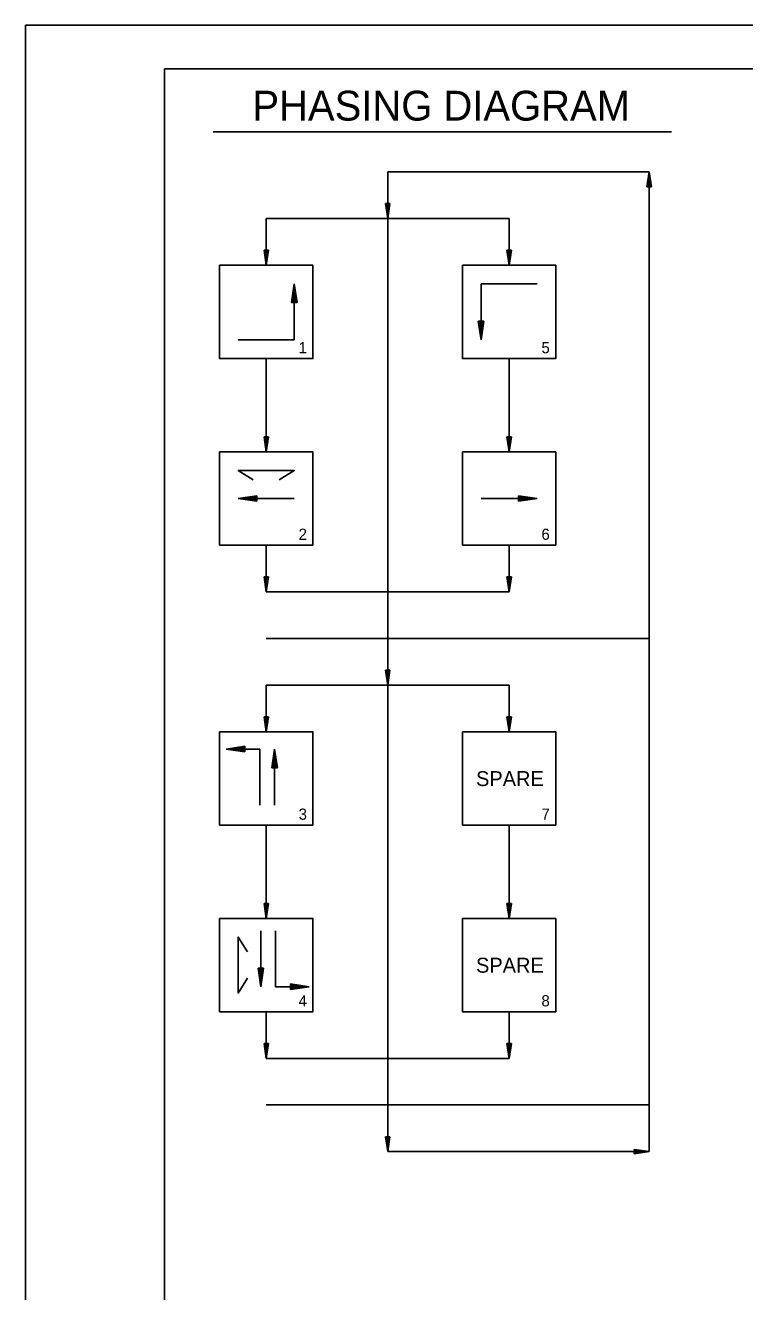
# Model space of a CAD drawing. Extents: x 660636 to 661659, y 641779 to 643841.
# Drawn here: x 660658.5 to 660851.1, y 642584.7 to 642924 of the extents above; entities that cross this region are included whole.
import ezdxf

# ---------------------------------------------------------------- set-up
doc = ezdxf.new("R2010")
doc.units = 0
for name, color, linetype in [('Default', 7, 'Continuous'), ('R_Border', 7, 'Continuous'), ('R_No Plot', 7, 'Continuous'), ('T_Drafting', 7, 'Continuous')]:
    doc.layers.add(name, color=color, linetype=linetype)

msp = doc.modelspace()

# ---------------------------------------------------------------- linework, layer by layer
at = {"layer": 'Default'}
for p, q in [((660708.78, 642895.44), (660831.43, 642895.44)), ((660824.91, 642880.72), (660825.51, 642884.72)), ((660825.01, 642880.72), (660825.51, 642884.05)), ((660825.11, 642880.72), (660825.51, 642883.37)), ((660826.11, 642880.72), (660825.51, 642884.72)), ((660826.01, 642880.72), (660825.51, 642884.05)), ((660825.91, 642880.72), (660825.51, 642883.37)), ((660824.91, 642880.72), (660826.11, 642880.72)), ((660825.21, 642880.72), (660825.51, 642882.7)), ((660825.32, 642880.72), (660825.51, 642882.02)), ((660825.42, 642880.72), (660825.51, 642881.35)), ((660825.81, 642880.72), (660825.51, 642882.7)), ((660825.71, 642880.72), (660825.51, 642882.02)), ((660825.6, 642880.72), (660825.51, 642881.35)), ((660754.91, 642876.22), (660755.51, 642872.22)), ((660756.11, 642876.22), (660754.91, 642876.22)), ((660755.01, 642876.22), (660755.51, 642872.89)), ((660755.11, 642876.22), (660755.51, 642873.58)), ((660755.21, 642876.22), (660755.51, 642874.24)), ((660755.31, 642876.22), (660755.51, 642874.92)), ((660755.42, 642876.22), (660755.51, 642875.59)), ((660756.11, 642876.22), (660755.51, 642872.22)), ((660755.7, 642876.22), (660755.51, 642874.92)), ((660755.91, 642876.22), (660755.51, 642873.58)), ((660756.01, 642876.22), (660755.51, 642872.89)), ((660755.81, 642876.22), (660755.51, 642874.24)), ((660755.6, 642876.22), (660755.51, 642875.59)), ((660722.41, 642863.72), (660723.01, 642859.72)), ((660723.61, 642863.72), (660722.41, 642863.72)), ((660722.51, 642863.72), (660723.01, 642860.39)), ((660722.61, 642863.72), (660723.01, 642861.08)), ((660722.71, 642863.72), (660723.01, 642861.74)), ((660722.81, 642863.72), (660723.01, 642862.42)), ((660722.92, 642863.72), (660723.01, 642863.09)), ((660723.61, 642863.72), (660723.01, 642859.72)), ((660723.2, 642863.72), (660723.01, 642862.42)), ((660723.41, 642863.72), (660723.01, 642861.08)), ((660723.51, 642863.72), (660723.01, 642860.39)), ((660723.31, 642863.72), (660723.01, 642861.74)), ((660723.1, 642863.72), (660723.01, 642863.09)), ((660787.41, 642863.72), (660788.01, 642859.72)), ((660788.61, 642863.72), (660787.41, 642863.72)), ((660787.51, 642863.72), (660788.01, 642860.39)), ((660787.61, 642863.72), (660788.01, 642861.08)), ((660787.71, 642863.72), (660788.01, 642861.74)), ((660787.81, 642863.72), (660788.01, 642862.42)), ((660787.92, 642863.72), (660788.01, 642863.09)), ((660788.61, 642863.72), (660788.01, 642859.72)), ((660788.2, 642863.72), (660788.01, 642862.42)), ((660788.41, 642863.72), (660788.01, 642861.08)), ((660788.51, 642863.72), (660788.01, 642860.39)), ((660788.31, 642863.72), (660788.01, 642861.74)), ((660788.1, 642863.72), (660788.01, 642863.09)), ((660722.41, 642813.72), (660723.01, 642809.72)), ((660723.61, 642813.72), (660722.41, 642813.72)), ((660722.51, 642813.72), (660723.01, 642810.39)), ((660722.61, 642813.72), (660723.01, 642811.08)), ((660722.71, 642813.72), (660723.01, 642811.74)), ((660722.81, 642813.72), (660723.01, 642812.42)), ((660722.92, 642813.72), (660723.01, 642813.09)), ((660723.61, 642813.72), (660723.01, 642809.72)), ((660723.2, 642813.72), (660723.01, 642812.42)), ((660723.41, 642813.72), (660723.01, 642811.08)), ((660723.51, 642813.72), (660723.01, 642810.39)), ((660723.31, 642813.72), (660723.01, 642811.74)), ((660723.1, 642813.72), (660723.01, 642813.09)), ((660787.41, 642813.72), (660788.01, 642809.72)), ((660788.61, 642813.72), (660787.41, 642813.72)), ((660787.51, 642813.72), (660788.01, 642810.39)), ((660787.61, 642813.72), (660788.01, 642811.08)), ((660787.71, 642813.72), (660788.01, 642811.74)), ((660787.81, 642813.72), (660788.01, 642812.42)), ((660787.92, 642813.72), (660788.01, 642813.09)), ((660788.61, 642813.72), (660788.01, 642809.72)), ((660788.2, 642813.72), (660788.01, 642812.42)), ((660788.41, 642813.72), (660788.01, 642811.08)), ((660788.51, 642813.72), (660788.01, 642810.39)), ((660788.31, 642813.72), (660788.01, 642811.74)), ((660788.1, 642813.72), (660788.01, 642813.09)), ((660722.41, 642776.22), (660723.01, 642772.22)), ((660723.61, 642776.22), (660722.41, 642776.22)), ((660722.51, 642776.22), (660723.01, 642772.89)), ((660722.61, 642776.22), (660723.01, 642773.58)), ((660722.71, 642776.22), (660723.01, 642774.24)), ((660722.81, 642776.22), (660723.01, 642774.92)), ((660722.92, 642776.22), (660723.01, 642775.59)), ((660723.61, 642776.22), (660723.01, 642772.22)), ((660723.2, 642776.22), (660723.01, 642774.92)), ((660723.41, 642776.22), (660723.01, 642773.58)), ((660723.51, 642776.22), (660723.01, 642772.89)), ((660723.31, 642776.22), (660723.01, 642774.24)), ((660723.1, 642776.22), (660723.01, 642775.59)), ((660787.41, 642776.22), (660788.01, 642772.22)), ((660788.61, 642776.22), (660787.41, 642776.22)), ((660787.51, 642776.22), (660788.01, 642772.89)), ((660787.61, 642776.22), (660788.01, 642773.58)), ((660787.71, 642776.22), (660788.01, 642774.24)), ((660787.81, 642776.22), (660788.01, 642774.92)), ((660787.92, 642776.22), (660788.01, 642775.59)), ((660788.61, 642776.22), (660788.01, 642772.22)), ((660788.2, 642776.22), (660788.01, 642774.92)), ((660788.41, 642776.22), (660788.01, 642773.58)), ((660788.51, 642776.22), (660788.01, 642772.89)), ((660788.31, 642776.22), (660788.01, 642774.24)), ((660788.1, 642776.22), (660788.01, 642775.59)), ((660754.91, 642751.22), (660755.51, 642747.22)), ((660756.11, 642751.22), (660754.91, 642751.22)), ((660755.01, 642751.22), (660755.51, 642747.89)), ((660755.11, 642751.22), (660755.51, 642748.58)), ((660755.21, 642751.22), (660755.51, 642749.24)), ((660755.31, 642751.22), (660755.51, 642749.92)), ((660755.42, 642751.22), (660755.51, 642750.59)), ((660756.11, 642751.22), (660755.51, 642747.22)), ((660755.7, 642751.22), (660755.51, 642749.92)), ((660755.91, 642751.22), (660755.51, 642748.58)), ((660756.01, 642751.22), (660755.51, 642747.89)), ((660755.81, 642751.22), (660755.51, 642749.24)), ((660755.6, 642751.22), (660755.51, 642750.59)), ((660722.41, 642738.72), (660723.01, 642734.72)), ((660723.61, 642738.72), (660722.41, 642738.72)), ((660722.51, 642738.72), (660723.01, 642735.39)), ((660722.61, 642738.72), (660723.01, 642736.08)), ((660722.71, 642738.72), (660723.01, 642736.74)), ((660722.81, 642738.72), (660723.01, 642737.42)), ((660722.92, 642738.72), (660723.01, 642738.09)), ((660723.61, 642738.72), (660723.01, 642734.72)), ((660723.2, 642738.72), (660723.01, 642737.42)), ((660723.41, 642738.72), (660723.01, 642736.08)), ((660723.51, 642738.72), (660723.01, 642735.39)), ((660723.31, 642738.72), (660723.01, 642736.74)), ((660723.1, 642738.72), (660723.01, 642738.09)), ((660787.41, 642738.72), (660788.01, 642734.72)), ((660788.61, 642738.72), (660787.41, 642738.72)), ((660787.51, 642738.72), (660788.01, 642735.39)), ((660787.61, 642738.72), (660788.01, 642736.08)), ((660787.71, 642738.72), (660788.01, 642736.74)), ((660787.81, 642738.72), (660788.01, 642737.42)), ((660787.92, 642738.72), (660788.01, 642738.09)), ((660788.61, 642738.72), (660788.01, 642734.72)), ((660788.2, 642738.72), (660788.01, 642737.42)), ((660788.41, 642738.72), (660788.01, 642736.08)), ((660788.51, 642738.72), (660788.01, 642735.39)), ((660788.31, 642738.72), (660788.01, 642736.74)), ((660788.1, 642738.72), (660788.01, 642738.09)), ((660722.41, 642688.72), (660723.01, 642684.72)), ((660723.61, 642688.72), (660722.41, 642688.72)), ((660722.51, 642688.72), (660723.01, 642685.39)), ((660722.61, 642688.72), (660723.01, 642686.08)), ((660722.71, 642688.72), (660723.01, 642686.74)), ((660722.81, 642688.72), (660723.01, 642687.42)), ((660722.92, 642688.72), (660723.01, 642688.09)), ((660723.61, 642688.72), (660723.01, 642684.72)), ((660723.2, 642688.72), (660723.01, 642687.42)), ((660723.41, 642688.72), (660723.01, 642686.08)), ((660723.51, 642688.72), (660723.01, 642685.39)), ((660723.31, 642688.72), (660723.01, 642686.74)), ((660723.1, 642688.72), (660723.01, 642688.09)), ((660787.41, 642688.72), (660788.01, 642684.72)), ((660788.61, 642688.72), (660787.41, 642688.72)), ((660787.51, 642688.72), (660788.01, 642685.39)), ((660787.61, 642688.72), (660788.01, 642686.08)), ((660787.71, 642688.72), (660788.01, 642686.74)), ((660787.81, 642688.72), (660788.01, 642687.42)), ((660787.92, 642688.72), (660788.01, 642688.09)), ((660788.61, 642688.72), (660788.01, 642684.72)), ((660788.2, 642688.72), (660788.01, 642687.42)), ((660788.41, 642688.72), (660788.01, 642686.08)), ((660788.51, 642688.72), (660788.01, 642685.39)), ((660788.31, 642688.72), (660788.01, 642686.74)), ((660788.1, 642688.72), (660788.01, 642688.09)), ((660722.41, 642651.22), (660723.01, 642647.22)), ((660723.61, 642651.22), (660722.41, 642651.22)), ((660722.51, 642651.22), (660723.01, 642647.89)), ((660722.61, 642651.22), (660723.01, 642648.58)), ((660722.71, 642651.22), (660723.01, 642649.24)), ((660722.81, 642651.22), (660723.01, 642649.92)), ((660722.92, 642651.22), (660723.01, 642650.59)), ((660723.61, 642651.22), (660723.01, 642647.22)), ((660723.2, 642651.22), (660723.01, 642649.92)), ((660723.41, 642651.22), (660723.01, 642648.58)), ((660723.51, 642651.22), (660723.01, 642647.89)), ((660723.31, 642651.22), (660723.01, 642649.24)), ((660723.1, 642651.22), (660723.01, 642650.59)), ((660787.41, 642651.22), (660788.01, 642647.22)), ((660788.61, 642651.22), (660787.41, 642651.22)), ((660787.51, 642651.22), (660788.01, 642647.89)), ((660787.61, 642651.22), (660788.01, 642648.58)), ((660787.71, 642651.22), (660788.01, 642649.24)), ((660787.81, 642651.22), (660788.01, 642649.92)), ((660787.92, 642651.22), (660788.01, 642650.59)), ((660788.61, 642651.22), (660788.01, 642647.22)), ((660788.2, 642651.22), (660788.01, 642649.92)), ((660788.41, 642651.22), (660788.01, 642648.58)), ((660788.51, 642651.22), (660788.01, 642647.89)), ((660788.31, 642651.22), (660788.01, 642649.24)), ((660788.1, 642651.22), (660788.01, 642650.59)), ((660754.91, 642626.22), (660755.51, 642622.22)), ((660756.11, 642626.22), (660754.91, 642626.22)), ((660755.01, 642626.22), (660755.51, 642622.89)), ((660755.11, 642626.22), (660755.51, 642623.58)), ((660755.21, 642626.22), (660755.51, 642624.24)), ((660755.31, 642626.22), (660755.51, 642624.92)), ((660755.42, 642626.22), (660755.51, 642625.59)), ((660756.11, 642626.22), (660755.51, 642622.22)), ((660755.7, 642626.22), (660755.51, 642624.92)), ((660755.91, 642626.22), (660755.51, 642623.58)), ((660756.01, 642626.22), (660755.51, 642622.89)), ((660755.81, 642626.22), (660755.51, 642624.24)), ((660755.6, 642626.22), (660755.51, 642625.59)), ((660821.51, 642622.82), (660825.51, 642622.22)), ((660821.51, 642622.82), (660821.51, 642621.62)), ((660821.51, 642622.72), (660824.84, 642622.22)), ((660821.51, 642622.62), (660824.15, 642622.22)), ((660821.51, 642622.52), (660823.49, 642622.22)), ((660821.51, 642622.42), (660822.81, 642622.22)), ((660821.51, 642622.32), (660822.14, 642622.22)), ((660821.51, 642621.62), (660825.51, 642622.22)), ((660821.51, 642622.03), (660822.81, 642622.22)), ((660821.51, 642621.82), (660824.15, 642622.22)), ((660821.51, 642621.72), (660824.84, 642622.22)), ((660821.51, 642621.92), (660823.49, 642622.22)), ((660821.51, 642622.13), (660822.14, 642622.22))]:
    msp.add_line(p, q, dxfattribs=at)
at = {"layer": 'R_Border'}
for p, q in [((660695.76, 642912.31), (661644.3, 642912.31)), ((660695.76, 642295.93), (660695.76, 642912.31))]:
    msp.add_line(p, q, dxfattribs=at)
at = {"layer": 'R_No Plot'}
msp.add_line((660658.55, 642924), (661658.55, 642924), dxfattribs=at)
msp.add_lwpolyline([(660658.53, 642924), (661658.55, 642924), (661658.55, 642283.98), (660658.53, 642283.98)], close=True, dxfattribs=at)
at = {"layer": 'T_Drafting'}
for p, q in [((660755.51, 642622.22), (660755.51, 642884.72)), ((660755.51, 642884.72), (660825.51, 642884.72)), ((660825.51, 642884.72), (660825.51, 642622.22)), ((660723.01, 642859.72), (660723.01, 642872.22)), ((660723.01, 642872.22), (660788.01, 642872.22)), ((660788.01, 642859.72), (660788.01, 642872.22)), ((660729.76, 642849.72), (660730.51, 642854.72)), ((660730.51, 642853.89), (660729.88, 642849.72)), ((660730.01, 642849.72), (660730.51, 642853.03)), ((660730.51, 642839.72), (660730.51, 642854.72)), ((660730.51, 642854.72), (660731.26, 642849.72)), ((660731.13, 642849.72), (660730.51, 642853.89)), ((660730.51, 642853.03), (660731.01, 642849.72)), ((660795.51, 642854.72), (660780.51, 642854.72)), ((660780.51, 642854.72), (660780.51, 642839.72)), ((660729.76, 642849.72), (660731.26, 642849.72)), ((660730.51, 642852.19), (660730.14, 642849.72)), ((660730.27, 642849.72), (660730.51, 642851.35)), ((660730.51, 642850.51), (660730.39, 642849.72)), ((660730.88, 642849.72), (660730.51, 642852.19)), ((660730.51, 642851.35), (660730.75, 642849.72)), ((660730.63, 642849.72), (660730.51, 642850.51)), ((660780.51, 642839.72), (660779.76, 642844.72)), ((660781.26, 642844.72), (660779.76, 642844.72)), ((660779.88, 642844.72), (660780.51, 642840.56)), ((660780.51, 642841.42), (660780.01, 642844.72)), ((660780.14, 642844.72), (660780.51, 642842.25)), ((660780.51, 642843.1), (660780.26, 642844.72)), ((660780.39, 642844.72), (660780.51, 642843.93)), ((660780.51, 642843.93), (660780.63, 642844.72)), ((660780.75, 642844.72), (660780.51, 642843.1)), ((660780.51, 642842.25), (660780.88, 642844.72)), ((660781.01, 642844.72), (660780.51, 642841.42)), ((660780.51, 642840.56), (660781.13, 642844.72)), ((660781.26, 642844.72), (660780.51, 642839.72)), ((660715.51, 642839.72), (660730.51, 642839.72)), ((660723.01, 642809.72), (660723.01, 642834.72)), ((660788.01, 642809.72), (660788.01, 642834.72)), ((660715.51, 642797.22), (660720.51, 642797.97)), ((660720.51, 642796.47), (660720.51, 642797.97)), ((660795.51, 642797.22), (660790.51, 642797.97)), ((660790.51, 642796.47), (660790.51, 642797.97)), ((660730.51, 642797.22), (660715.51, 642797.22)), ((660720.51, 642796.47), (660715.51, 642797.22)), ((660720.51, 642797.85), (660716.34, 642797.22)), ((660716.34, 642797.22), (660720.51, 642796.6)), ((660717.2, 642797.22), (660720.51, 642797.72)), ((660720.51, 642796.72), (660717.2, 642797.22)), ((660720.51, 642797.59), (660718.04, 642797.22)), ((660718.04, 642797.22), (660720.51, 642796.85)), ((660718.88, 642797.22), (660720.51, 642797.47)), ((660720.51, 642796.98), (660718.88, 642797.22)), ((660720.51, 642797.34), (660719.72, 642797.22)), ((660719.72, 642797.22), (660720.51, 642797.1)), ((660780.51, 642797.22), (660795.51, 642797.22)), ((660790.51, 642797.85), (660794.67, 642797.22)), ((660793.81, 642797.22), (660790.51, 642797.72)), ((660790.51, 642797.59), (660792.98, 642797.22)), ((660792.13, 642797.22), (660790.51, 642797.47)), ((660790.51, 642797.34), (660791.3, 642797.22)), ((660791.3, 642797.22), (660790.51, 642797.1)), ((660790.51, 642796.98), (660792.13, 642797.22)), ((660792.98, 642797.22), (660790.51, 642796.85)), ((660790.51, 642796.72), (660793.81, 642797.22)), ((660794.67, 642797.22), (660790.51, 642796.6)), ((660790.51, 642796.47), (660795.51, 642797.22)), ((660723.01, 642772.22), (660723.01, 642784.72)), ((660788.01, 642772.22), (660788.01, 642784.72)), ((660723.01, 642772.22), (660788.01, 642772.22)), ((660723.01, 642759.72), (660825.51, 642759.72)), ((660723.01, 642747.22), (660788.01, 642747.22)), ((660723.01, 642734.72), (660723.01, 642747.22)), ((660788.01, 642734.72), (660788.01, 642747.22)), ((660717.31, 642730.84), (660712.31, 642730.09)), ((660712.31, 642730.09), (660721.31, 642730.09)), ((660712.31, 642730.09), (660717.31, 642729.34)), ((660713.15, 642730.09), (660717.31, 642730.71)), ((660717.31, 642729.46), (660713.15, 642730.09)), ((660717.31, 642730.58), (660714.01, 642730.09)), ((660714.01, 642730.09), (660717.31, 642729.59)), ((660714.84, 642730.09), (660717.31, 642730.46)), ((660717.31, 642729.71), (660714.84, 642730.09)), ((660717.31, 642730.33), (660715.69, 642730.09)), ((660715.69, 642730.09), (660717.31, 642729.84)), ((660716.52, 642730.09), (660717.31, 642730.2)), ((660717.31, 642729.97), (660716.52, 642730.09)), ((660717.31, 642730.84), (660717.31, 642729.34)), ((660721.31, 642730.09), (660721.31, 642715.09)), ((660724.51, 642725.09), (660725.26, 642730.09)), ((660725.26, 642715.09), (660725.26, 642730.09)), ((660725.26, 642730.09), (660726.01, 642725.09)), ((660725.26, 642729.25), (660724.64, 642725.09)), ((660724.76, 642725.09), (660725.26, 642728.39)), ((660725.26, 642727.56), (660724.89, 642725.09)), ((660725.02, 642725.09), (660725.26, 642726.71)), ((660725.89, 642725.09), (660725.26, 642729.25)), ((660725.26, 642728.39), (660725.76, 642725.09)), ((660725.63, 642725.09), (660725.26, 642727.56)), ((660725.26, 642726.71), (660725.51, 642725.09)), ((660724.51, 642725.09), (660726.01, 642725.09)), ((660725.26, 642725.88), (660725.14, 642725.09)), ((660725.38, 642725.09), (660725.26, 642725.88)), ((660723.01, 642684.72), (660723.01, 642709.72)), ((660788.01, 642684.72), (660788.01, 642709.72)), ((660721.56, 642681.39), (660721.56, 642666.39)), ((660725.51, 642666.39), (660725.51, 642681.39)), ((660721.56, 642666.39), (660720.81, 642671.39)), ((660722.31, 642671.39), (660720.81, 642671.39)), ((660720.93, 642671.39), (660721.56, 642667.23)), ((660721.56, 642668.09), (660721.06, 642671.39)), ((660721.19, 642671.39), (660721.56, 642668.92)), ((660721.56, 642669.77), (660721.31, 642671.39)), ((660721.44, 642671.39), (660721.56, 642670.6)), ((660721.56, 642670.6), (660721.68, 642671.39)), ((660721.8, 642671.39), (660721.56, 642669.77)), ((660721.56, 642668.92), (660721.93, 642671.39)), ((660722.06, 642671.39), (660721.56, 642668.09)), ((660721.56, 642667.23), (660722.18, 642671.39)), ((660722.31, 642671.39), (660721.56, 642666.39)), ((660734.51, 642666.39), (660725.51, 642666.39)), ((660734.51, 642666.39), (660729.51, 642667.14)), ((660729.51, 642665.64), (660729.51, 642667.14)), ((660729.51, 642667.02), (660733.67, 642666.39)), ((660732.81, 642666.39), (660729.51, 642666.89)), ((660729.51, 642666.76), (660731.98, 642666.39)), ((660731.13, 642666.39), (660729.51, 642666.64)), ((660729.51, 642666.51), (660730.3, 642666.39)), ((660730.3, 642666.39), (660729.51, 642666.27)), ((660729.51, 642666.15), (660731.13, 642666.39)), ((660731.98, 642666.39), (660729.51, 642666.02)), ((660729.51, 642665.89), (660732.81, 642666.39)), ((660733.67, 642666.39), (660729.51, 642665.77)), ((660729.51, 642665.64), (660734.51, 642666.39)), ((660723.01, 642647.22), (660723.01, 642659.72)), ((660788.01, 642647.22), (660788.01, 642659.72)), ((660723.01, 642647.22), (660788.01, 642647.22)), ((660723.01, 642634.72), (660825.51, 642634.72)), ((660755.51, 642622.22), (660825.51, 642622.22))]:
    msp.add_line(p, q, dxfattribs=at)
for points in [[(660710.51, 642859.72), (660735.51, 642859.72), (660735.51, 642834.72), (660710.51, 642834.72)], [(660775.51, 642859.72), (660800.51, 642859.72), (660800.51, 642834.72), (660775.51, 642834.72)], [(660710.51, 642809.72), (660735.51, 642809.72), (660735.51, 642784.72), (660710.51, 642784.72)], [(660775.51, 642809.72), (660800.51, 642809.72), (660800.51, 642784.72), (660775.51, 642784.72)], [(660710.51, 642734.72), (660735.51, 642734.72), (660735.51, 642709.72), (660710.51, 642709.72)], [(660775.51, 642734.72), (660800.51, 642734.72), (660800.51, 642709.72), (660775.51, 642709.72)], [(660710.51, 642684.72), (660735.51, 642684.72), (660735.51, 642659.72), (660710.51, 642659.72)], [(660775.51, 642684.72), (660800.51, 642684.72), (660800.51, 642659.72), (660775.51, 642659.72)]]:
    msp.add_lwpolyline(points, close=True, dxfattribs=at)
for points in [[(660719.51, 642802.22), (660715.51, 642804.72), (660730.51, 642804.72), (660726.51, 642802.22)], [(660718.01, 642668.72), (660715.51, 642664.72), (660715.51, 642679.72), (660718.01, 642675.72)]]:
    msp.add_lwpolyline(points, dxfattribs=at)

# ---------------------------------------------------------------- texts
at = {"layer": 'Default'}
for s, height, p in [('PHASING DIAGRAM', 8, (660719.31, 642898.47)), ('1', 3, (660731.67, 642836.14)), ('5', 3, (660796.67, 642836.14)), ('2', 3, (660731.67, 642786.14)), ('6', 3, (660796.67, 642786.14)), ('3', 3, (660731.67, 642711.14)), ('7', 3, (660796.67, 642711.14)), ('4', 3, (660731.67, 642661.14)), ('8', 3, (660796.67, 642661.14))]:
    msp.add_text(s, height=height, dxfattribs=at).set_placement(p)
at = {"layer": 'T_Drafting'}
for p in [(660779.16, 642720.17), (660779.16, 642670.17)]:
    msp.add_text('SPARE', height=4, dxfattribs=at).set_placement(p)

doc.saveas('drawing.dxf')
